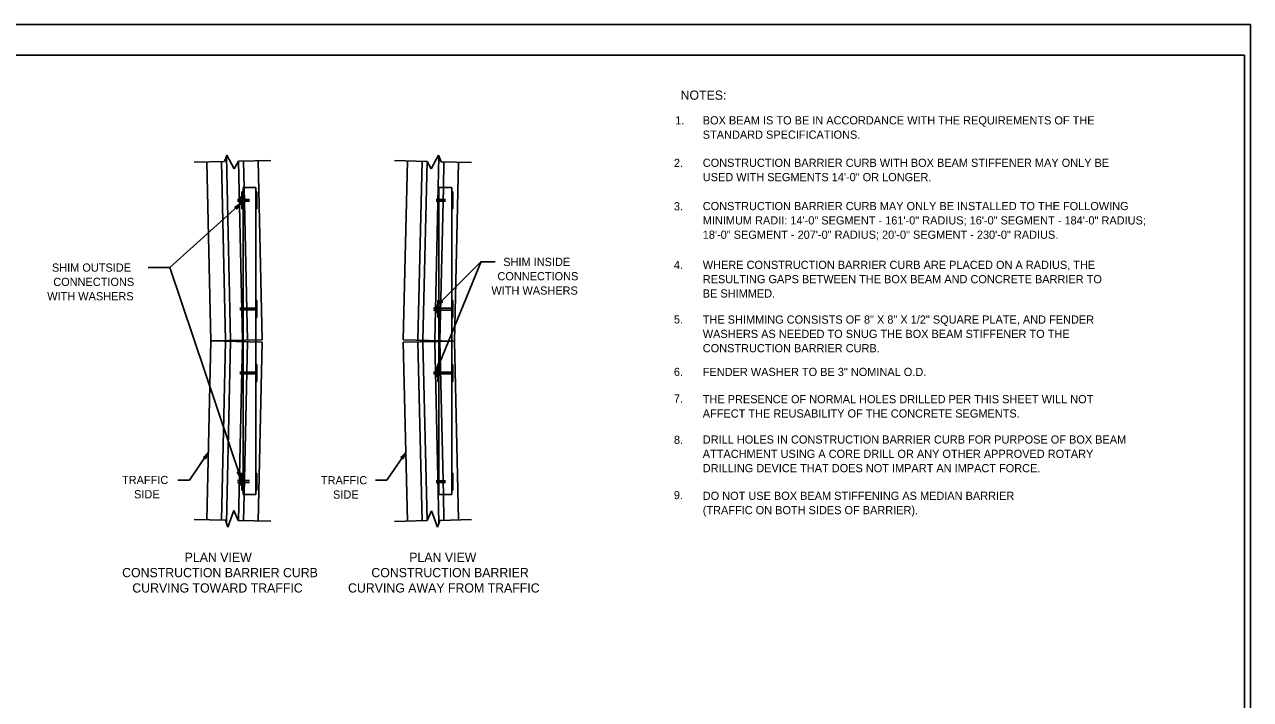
# Model space of a CAD drawing. Extents: x 499881 to 500993, y 499985 to 500645.
# Drawn here: x 500394 to 500993, y 500315 to 500645 of the extents above; entities that cross this region are included whole.
import ezdxf

# ---------------------------------------------------------------- set-up
doc = ezdxf.new("R2010")
doc.units = 0
for name, color, linetype in [('1', 7, 'Continuous'), ('2', 7, 'Continuous'), ('3', 7, 'Continuous'), ('41', 7, 'Continuous'), ('5', 7, 'Continuous')]:
    doc.layers.add(name, color=color, linetype=linetype)

msp = doc.modelspace()

# ---------------------------------------------------------------- linework, layer by layer
at = {"layer": '1'}
for p, q in [((499944.83, 500645), (500993, 500645)), ((500990, 500630), (500000, 500630)), ((500990, 500000), (500990, 500630))]:
    msp.add_line(p, q, dxfattribs=at)
at = {"layer": '2'}
for points in [[(500499.74, 500557.5), (500496.89, 500555.69), (500497.87, 500555.79), (500497.69, 500554.84), (500499.74, 500557.5), (500499.58, 500557.34), (500496.99, 500555.72), (500497.92, 500555.83), (500497.76, 500554.96), (500499.5, 500557.25), (500499.41, 500557.19), (500497.19, 500555.79), (500497.93, 500555.84), (500497.8, 500555.1), (500499.37, 500557.16), (500499.3, 500557.07), (500497.36, 500555.85), (500497.95, 500555.86), (500497.89, 500555.26), (500499.06, 500556.85), (500498.92, 500556.73), (500497.54, 500555.9), (500497.97, 500555.89), (500497.94, 500555.42), (500498.89, 500556.72), (500498.75, 500556.61), (500497.73, 500555.96), (500498.06, 500555.94), (500498.03, 500555.6), (500498.63, 500556.49), (500498.5, 500556.39), (500497.88, 500556.01), (500498.08, 500555.97), (500498.05, 500555.71), (500498.45, 500556.32), (500498.03, 500556.08), (500498.16, 500556.04), (500498.1, 500555.8), (500498.37, 500556.23), (500498.1, 500556.08), (500498.26, 500556.09), (500498.19, 500555.94), (500498.23, 500556.11), (500498.17, 500556.07)], [(500595.49, 500507.42), (500598.25, 500509.37), (500597.27, 500509.22), (500597.41, 500510.18), (500595.49, 500507.42), (500595.64, 500507.58), (500598.15, 500509.33), (500597.22, 500509.18), (500597.34, 500510.05), (500595.71, 500507.67), (500595.8, 500507.74), (500597.95, 500509.25), (500597.21, 500509.17), (500597.31, 500509.91), (500595.84, 500507.78), (500595.91, 500507.87), (500597.78, 500509.18), (500597.2, 500509.14), (500597.22, 500509.75), (500596.13, 500508.1), (500596.26, 500508.23), (500597.61, 500509.12), (500597.18, 500509.11), (500597.18, 500509.58), (500596.3, 500508.24), (500596.43, 500508.36), (500597.41, 500509.06), (500597.09, 500509.06), (500597.1, 500509.39), (500596.54, 500508.48), (500596.67, 500508.59), (500597.27, 500509), (500597.07, 500509.03), (500597.08, 500509.29), (500596.72, 500508.66), (500597.12, 500508.91), (500596.99, 500508.96), (500597.04, 500509.19), (500596.79, 500508.76), (500597.06, 500508.92), (500596.9, 500508.9), (500596.96, 500509.05), (500596.92, 500508.88), (500596.99, 500508.92)], [(500595.49, 500476.18), (500597.35, 500478.99), (500596.5, 500478.5), (500596.28, 500479.44), (500595.49, 500476.18), (500595.57, 500476.39), (500597.28, 500478.92), (500596.47, 500478.45), (500596.27, 500479.3), (500595.61, 500476.5), (500595.67, 500476.59), (500597.12, 500478.77), (500596.46, 500478.43), (500596.29, 500479.16), (500595.69, 500476.64), (500595.72, 500476.75), (500596.99, 500478.65), (500596.46, 500478.41), (500596.27, 500478.98), (500595.84, 500477.04), (500595.92, 500477.21), (500596.85, 500478.53), (500596.45, 500478.37), (500596.28, 500478.8), (500595.95, 500477.24), (500596.03, 500477.4), (500596.69, 500478.4), (500596.39, 500478.29), (500596.28, 500478.6), (500596.08, 500477.55), (500596.17, 500477.7), (500596.58, 500478.3), (500596.38, 500478.25), (500596.3, 500478.5), (500596.19, 500477.78), (500596.47, 500478.16), (500596.33, 500478.15), (500596.29, 500478.39), (500596.22, 500477.9), (500596.41, 500478.15), (500596.27, 500478.07), (500596.27, 500478.23), (500596.3, 500478.06), (500596.34, 500478.12)], [(500483.91, 500435.78), (500481.57, 500433.34), (500482.5, 500433.67), (500482.55, 500432.7), (500483.91, 500435.78), (500483.79, 500435.59), (500481.66, 500433.39), (500482.54, 500433.72), (500482.59, 500432.84), (500483.73, 500435.48), (500483.66, 500435.4), (500481.85, 500433.51), (500482.55, 500433.73), (500482.6, 500432.99), (500483.63, 500435.36), (500483.58, 500435.26), (500481.99, 500433.61), (500482.56, 500433.76), (500482.65, 500433.16), (500483.4, 500434.99), (500483.3, 500434.84), (500482.16, 500433.7), (500482.57, 500433.79), (500482.66, 500433.33), (500483.27, 500434.82), (500483.16, 500434.67), (500482.33, 500433.8), (500482.65, 500433.86), (500482.7, 500433.53), (500483.08, 500434.53), (500482.97, 500434.4), (500482.46, 500433.89), (500482.66, 500433.89), (500482.7, 500433.64), (500482.94, 500434.32), (500482.59, 500434), (500482.73, 500433.98), (500482.72, 500433.74), (500482.89, 500434.22), (500482.65, 500434), (500482.81, 500434.05), (500482.78, 500433.9), (500482.78, 500434.07), (500482.72, 500434.02)], [(500580.31, 500435.78), (500577.95, 500433.37), (500578.88, 500433.69), (500578.92, 500432.72), (500580.31, 500435.78), (500580.19, 500435.59), (500578.04, 500433.42), (500578.93, 500433.74), (500578.96, 500432.86), (500580.14, 500435.49), (500580.06, 500435.4), (500578.22, 500433.54), (500578.94, 500433.75), (500578.97, 500433), (500580.03, 500435.36), (500579.98, 500435.26), (500578.37, 500433.63), (500578.94, 500433.77), (500579.02, 500433.18), (500579.8, 500435), (500579.69, 500434.84), (500578.54, 500433.72), (500578.96, 500433.81), (500579.04, 500433.35), (500579.66, 500434.82), (500579.55, 500434.68), (500578.72, 500433.82), (500579.03, 500433.88), (500579.08, 500433.54), (500579.47, 500434.54), (500579.36, 500434.41), (500578.85, 500433.9), (500579.05, 500433.91), (500579.08, 500433.65), (500579.33, 500434.33), (500578.97, 500434.01), (500579.12, 500434), (500579.11, 500433.76), (500579.27, 500434.23), (500579.04, 500434.02), (500579.19, 500434.07), (500579.16, 500433.91), (500579.17, 500434.09), (500579.11, 500434.03)], [(500499.74, 500423.11), (500499.23, 500426.45), (500498.93, 500425.51), (500498.13, 500426.06), (500499.74, 500423.11), (500499.66, 500423.32), (500499.22, 500426.35), (500498.94, 500425.45), (500498.22, 500425.95), (500499.61, 500423.43), (500499.59, 500423.54), (500499.2, 500426.13), (500498.95, 500425.43), (500498.33, 500425.85), (500499.58, 500423.59), (500499.53, 500423.69), (500499.19, 500425.95), (500498.96, 500425.41), (500498.43, 500425.71), (500499.42, 500423.99), (500499.36, 500424.17), (500499.17, 500425.77), (500498.98, 500425.38), (500498.56, 500425.59), (500499.37, 500424.21), (500499.32, 500424.38), (500499.14, 500425.57), (500498.99, 500425.28), (500498.7, 500425.44), (500499.26, 500424.53), (500499.22, 500424.69), (500499.12, 500425.41), (500499.01, 500425.25), (500498.78, 500425.38), (500499.18, 500424.77), (500499.13, 500425.25), (500499.04, 500425.14), (500498.85, 500425.29), (500499.13, 500424.88), (500499.1, 500425.19), (500499.05, 500425.04), (500498.94, 500425.16), (500499.08, 500425.05), (500499.07, 500425.13)]]:
    msp.add_lwpolyline(points, dxfattribs=at)
at = {"layer": '3'}
for p, q in [((500491.74, 500577.98), (500492.99, 500581.17)), ((500492.99, 500581.17), (500496.56, 500574.43)), ((500596.34, 500581.12), (500592.77, 500574.38)), ((500597.6, 500577.93), (500596.34, 500581.12)), ((500476.94, 500577.64), (500491.74, 500577.98)), ((500483.19, 500577.79), (500485.21, 500490.31)), ((500490.33, 500577.95), (500492.35, 500490.47)), ((500492.74, 500580.54), (500494.82, 500490.53)), ((500496.56, 500574.43), (500498.57, 500578.14)), ((500498.57, 500578.14), (500514.43, 500578.51)), ((500498.57, 500578.14), (500500.59, 500490.67)), ((500501.05, 500578.2), (500501.34, 500565.28)), ((500508.18, 500578.36), (500510.2, 500490.89)), ((500590.77, 500578.09), (500574.91, 500578.46)), ((500581.15, 500578.32), (500579.13, 500490.84)), ((500588.29, 500578.15), (500586.27, 500490.68)), ((500590.77, 500578.09), (500588.75, 500490.62)), ((500592.77, 500574.38), (500590.77, 500578.09)), ((500596.59, 500580.49), (500594.51, 500490.49)), ((500612.4, 500577.6), (500597.6, 500577.94)), ((500599.01, 500577.9), (500598.72, 500565.23)), ((500606.15, 500577.74), (500604.13, 500490.26)), ((500500.33, 500563.22), (500500.85, 500563.22)), ((500500.33, 500554.88), (500500.33, 500563.22)), ((500507.1, 500565.28), (500500.85, 500565.28)), ((500500.85, 500565.28), (500500.85, 500415.28)), ((500507.1, 500415.28), (500507.1, 500565.28)), ((500507.62, 500563.22), (500507.1, 500563.22)), ((500507.62, 500554.89), (500507.62, 500563.22)), ((500602.84, 500565.24), (500596.59, 500565.24)), ((500596.59, 500565.24), (500596.59, 500415.24)), ((500602.84, 500415.24), (500602.84, 500565.24)), ((500603.37, 500563.18), (500602.84, 500563.18)), ((500603.37, 500554.84), (500603.37, 500563.18)), ((500499.74, 500557.5), (500465.09, 500526.2)), ((500499.15, 500557.5), (500499.15, 500560.62)), ((500500.33, 500560.62), (500499.15, 500560.62)), ((500500.33, 500557.5), (500499.15, 500557.5)), ((500499.54, 500557.5), (500499.54, 500560.62)), ((500499.93, 500557.5), (500499.93, 500560.62)), ((500500.33, 500554.88), (500500.85, 500554.88)), ((500507.62, 500554.89), (500507.1, 500554.89)), ((500603.37, 500554.84), (500602.84, 500554.84)), ((500595.49, 500507.42), (500617.12, 500529.07)), ((500617.12, 500529.07), (500595.49, 500476.18)), ((500617.13, 500529.05), (500624.04, 500529.05)), ((500465.09, 500526.2), (500454.54, 500526.2)), ((500465.09, 500526.2), (500499.74, 500423.11)), ((500500.33, 500501.74), (500500.33, 500510.07)), ((500500.33, 500510.07), (500500.85, 500510.07)), ((500507.62, 500510.08), (500507.1, 500510.08)), ((500507.62, 500501.75), (500507.62, 500510.08)), ((500596.07, 500501.7), (500596.07, 500510.03)), ((500596.07, 500510.03), (500596.59, 500510.03)), ((500603.37, 500510.03), (500602.84, 500510.03)), ((500603.37, 500501.7), (500603.37, 500510.03)), ((500596.07, 500507.42), (500594.9, 500507.42)), ((500594.9, 500504.3), (500594.9, 500507.42)), ((500596.07, 500504.3), (500594.9, 500504.3)), ((500595.29, 500504.3), (500595.29, 500507.42)), ((500595.68, 500504.3), (500595.68, 500507.42)), ((500500.33, 500501.74), (500500.85, 500501.74)), ((500507.62, 500501.75), (500507.1, 500501.75)), ((500596.07, 500501.7), (500596.59, 500501.7)), ((500603.37, 500501.7), (500602.84, 500501.7)), ((500483.19, 500402.83), (500485.21, 500490.31)), ((500485.21, 500490.31), (500510.2, 500490.89)), ((500485.21, 500490.31), (500510.2, 500489.73)), ((500490.33, 500402.67), (500492.35, 500490.14)), ((500492.77, 500401.34), (500494.82, 500490.09)), ((500498.57, 500402.48), (500500.59, 500489.95)), ((500508.18, 500402.26), (500510.2, 500489.73)), ((500604.13, 500490.26), (500579.13, 500490.84)), ((500604.13, 500490.26), (500579.13, 500489.69)), ((500581.15, 500402.21), (500579.13, 500489.69)), ((500588.29, 500402.37), (500586.27, 500489.85)), ((500590.77, 500402.43), (500588.75, 500489.91)), ((500596.56, 500401.3), (500594.51, 500490.04)), ((500606.15, 500402.79), (500604.13, 500490.26)), ((500500.33, 500470.49), (500500.33, 500478.82)), ((500500.33, 500478.82), (500500.85, 500478.82)), ((500507.62, 500478.83), (500507.1, 500478.83)), ((500507.62, 500470.5), (500507.62, 500478.83)), ((500596.07, 500476.18), (500594.9, 500476.18)), ((500594.9, 500473.06), (500594.9, 500476.18)), ((500595.29, 500473.06), (500595.29, 500476.18)), ((500595.68, 500473.06), (500595.68, 500476.18)), ((500596.07, 500470.45), (500596.07, 500478.78)), ((500596.07, 500478.78), (500596.59, 500478.78)), ((500603.37, 500478.78), (500602.84, 500478.78)), ((500603.37, 500470.45), (500603.37, 500478.78)), ((500500.33, 500470.49), (500500.85, 500470.49)), ((500507.62, 500470.5), (500507.1, 500470.5)), ((500596.07, 500473.06), (500594.9, 500473.06)), ((500596.07, 500470.45), (500596.59, 500470.45)), ((500603.37, 500470.45), (500602.84, 500470.45)), ((500483.91, 500435.78), (500474.74, 500422.31)), ((500580.31, 500435.78), (500571.14, 500422.31)), ((500500.33, 500417.38), (500500.33, 500425.71)), ((500500.33, 500425.71), (500500.85, 500425.71)), ((500507.62, 500425.72), (500507.1, 500425.72)), ((500507.62, 500417.38), (500507.62, 500425.72)), ((500603.37, 500425.67), (500602.84, 500425.67)), ((500603.37, 500417.34), (500603.37, 500425.67)), ((500474.74, 500422.31), (500469.09, 500422.31)), ((500500.33, 500423.11), (500499.15, 500423.11)), ((500499.15, 500419.99), (500499.15, 500423.11)), ((500500.33, 500419.99), (500499.15, 500419.99)), ((500499.54, 500419.99), (500499.54, 500423.11)), ((500499.93, 500419.99), (500499.93, 500423.11)), ((500571.14, 500422.31), (500565.5, 500422.31)), ((500500.33, 500417.38), (500500.85, 500417.38)), ((500500.85, 500415.28), (500507.1, 500415.28)), ((500501.05, 500402.42), (500501.34, 500415.28)), ((500507.62, 500417.38), (500507.1, 500417.38)), ((500596.59, 500415.24), (500602.84, 500415.24)), ((500599.01, 500402.62), (500598.72, 500415.24)), ((500603.37, 500417.34), (500602.84, 500417.34)), ((500476.94, 500402.98), (500492.35, 500402.62)), ((500492.34, 500402.62), (500493.45, 500399.33)), ((500493.45, 500399.33), (500496.41, 500407.32)), ((500496.41, 500407.32), (500498.56, 500402.48)), ((500498.56, 500402.48), (500514.43, 500402.11)), ((500590.77, 500402.43), (500574.91, 500402.06)), ((500592.92, 500407.27), (500590.77, 500402.43)), ((500595.89, 500399.28), (500592.92, 500407.27)), ((500596.99, 500402.57), (500595.89, 500399.28)), ((500612.4, 500402.93), (500596.99, 500402.57))]:
    msp.add_line(p, q, dxfattribs=at)
at = {"layer": '41'}
msp.add_lwpolyline([(499944.83, 499985), (500993, 499985), (500993, 500645), (499944.83, 500645)], close=True, dxfattribs=at)
at = {"layer": '5'}
for p, q in [((500501.34, 500565.28), (500503.07, 500490.72)), ((500598.72, 500565.21), (500596.99, 500490.43)), ((500503.97, 500559.51), (500498.09, 500559.51)), ((500503.97, 500558.6), (500498.11, 500558.6)), ((500599.72, 500558.55), (500595.17, 500558.55)), ((500599.72, 500559.47), (500595.19, 500559.47)), ((500507.1, 500506.36), (500499.32, 500506.36)), ((500507.1, 500505.45), (500499.34, 500505.45)), ((500602.84, 500505.41), (500593.94, 500505.41)), ((500602.84, 500506.32), (500593.97, 500506.32)), ((500501.34, 500415.28), (500503.07, 500489.9)), ((500598.72, 500415.26), (500596.99, 500490.1)), ((500507.1, 500474.2), (500499.31, 500474.2)), ((500507.1, 500475.11), (500499.33, 500475.11)), ((500602.84, 500475.07), (500593.95, 500475.07)), ((500602.84, 500474.16), (500593.97, 500474.16)), ((500503.98, 500421.09), (500498.09, 500421.09)), ((500503.98, 500422), (500498.11, 500422)), ((500599.72, 500421.95), (500595.17, 500421.95)), ((500599.72, 500421.04), (500595.19, 500421.04))]:
    msp.add_line(p, q, dxfattribs=at)

# ---------------------------------------------------------------- texts
at = {"layer": '3'}
for s, height, p in [('NOTES:', 4.5, (500714.61, 500608.21)), ('1.', 4, (500711.97, 500596.15)), ('BOX BEAM IS TO BE IN ACCORDANCE WITH THE REQUIREMENTS OF THE ', 4, (500725.44, 500596.15)), ('STANDARD SPECIFICATIONS.', 4, (500725.44, 500589.15)), ('2.', 4, (500711.36, 500575.32)), ('CONSTRUCTION BARRIER CURB WITH BOX BEAM STIFFENER MAY ONLY BE ', 4, (500725.44, 500575.4)), ('USED WITH SEGMENTS 14\'-0" OR LONGER.', 4, (500725.44, 500568.4)), ('3.', 4, (500711.34, 500554.14)), ('CONSTRUCTION BARRIER CURB MAY ONLY BE INSTALLED TO THE FOLLOWING ', 4, (500725.44, 500554.24)), ('MINIMUM RADII: 14\'-0" SEGMENT - 161\'-0" RADIUS; 16\'-0" SEGMENT - 184\'-0" RADIUS; ', 4, (500725.44, 500547.24)), ('18\'-0" SEGMENT - 207\'-0" RADIUS; 20\'-0" SEGMENT - 230\'-0" RADIUS.', 4, (500725.44, 500540.24)), ('SHIM OUTSIDE', 4, (500407.51, 500524.16)), ('SHIM INSIDE', 4, (500627.99, 500526.94)), ('4.', 4, (500711.31, 500525.42)), ('WHERE CONSTRUCTION BARRIER CURB ARE PLACED ON A RADIUS, THE ', 4, (500725.44, 500525.5)), ('CONNECTIONS', 4, (500408.16, 500517.16)), ('CONNECTIONS', 4, (500625.14, 500519.94)), ('RESULTING GAPS BETWEEN THE BOX BEAM AND CONCRETE BARRIER TO ', 4, (500725.44, 500518.5)), ('WITH WASHERS', 4, (500622.2, 500512.94)), ('BE SHIMMED.', 4, (500725.44, 500511.5)), ('WITH WASHERS', 4, (500405.22, 500510.16)), ('5.', 4, (500711.34, 500498.84)), ('THE SHIMMING CONSISTS OF 8" X 8" X 1/2" SQUARE PLATE, AND FENDER ', 4, (500725.44, 500498.75)), ('WASHERS AS NEEDED TO SNUG THE BOX BEAM STIFFENER TO THE ', 4, (500725.44, 500491.75)), ('CONSTRUCTION BARRIER CURB.', 4, (500725.44, 500484.75)), ('6.', 4, (500711.33, 500473.16)), ('FENDER WASHER TO BE 3" NOMINAL O.D.', 4, (500725.44, 500473.14)), ('7.', 4, (500711.36, 500460.18)), ('THE PRESENCE OF NORMAL HOLES DRILLED PER THIS SHEET WILL NOT ', 4, (500725.44, 500459.83)), ('AFFECT THE REUSABILITY OF THE CONCRETE SEGMENTS.', 4, (500725.44, 500452.83)), ('8.', 4, (500711.35, 500439.95)), ('DRILL HOLES IN CONSTRUCTION BARRIER CURB FOR PURPOSE OF BOX BEAM ', 4, (500725.44, 500440.11)), ('ATTACHMENT USING A CORE DRILL OR ANY OTHER APPROVED ROTARY ', 4, (500725.44, 500433.11)), ('DRILLING DEVICE THAT DOES NOT IMPART AN IMPACT FORCE.  ', 4, (500725.44, 500426.11)), ('TRAFFIC', 4, (500441.75, 500420.34)), ('TRAFFIC', 4, (500538.93, 500420.19)), ('SIDE', 4, (500447.64, 500413.34)), ('SIDE', 4, (500544.83, 500413.19)), ('9.', 4, (500711.33, 500412.95)), ('DO NOT USE BOX BEAM STIFFENING AS MEDIAN BARRIER', 4, (500725.44, 500412.59)), ('(TRAFFIC ON BOTH SIDES OF BARRIER).', 4, (500725.44, 500405.59))]:
    msp.add_text(s, height=height, dxfattribs=at).set_placement(p)
at = {"layer": '5'}
for s, p in [('PLAN VIEW', (500472.34, 500382.29)), ('PLAN VIEW ', (500582.06, 500382.29)), ('CONSTRUCTION BARRIER CURB', (500441.81, 500374.79)), ('CONSTRUCTION BARRIER', (500563.56, 500374.79)), ('CURVING TOWARD TRAFFIC', (500446.77, 500367.29)), ('CURVING AWAY FROM TRAFFIC', (500552.16, 500367.29))]:
    msp.add_text(s, height=4.5, dxfattribs=at).set_placement(p)

doc.saveas('drawing.dxf')
